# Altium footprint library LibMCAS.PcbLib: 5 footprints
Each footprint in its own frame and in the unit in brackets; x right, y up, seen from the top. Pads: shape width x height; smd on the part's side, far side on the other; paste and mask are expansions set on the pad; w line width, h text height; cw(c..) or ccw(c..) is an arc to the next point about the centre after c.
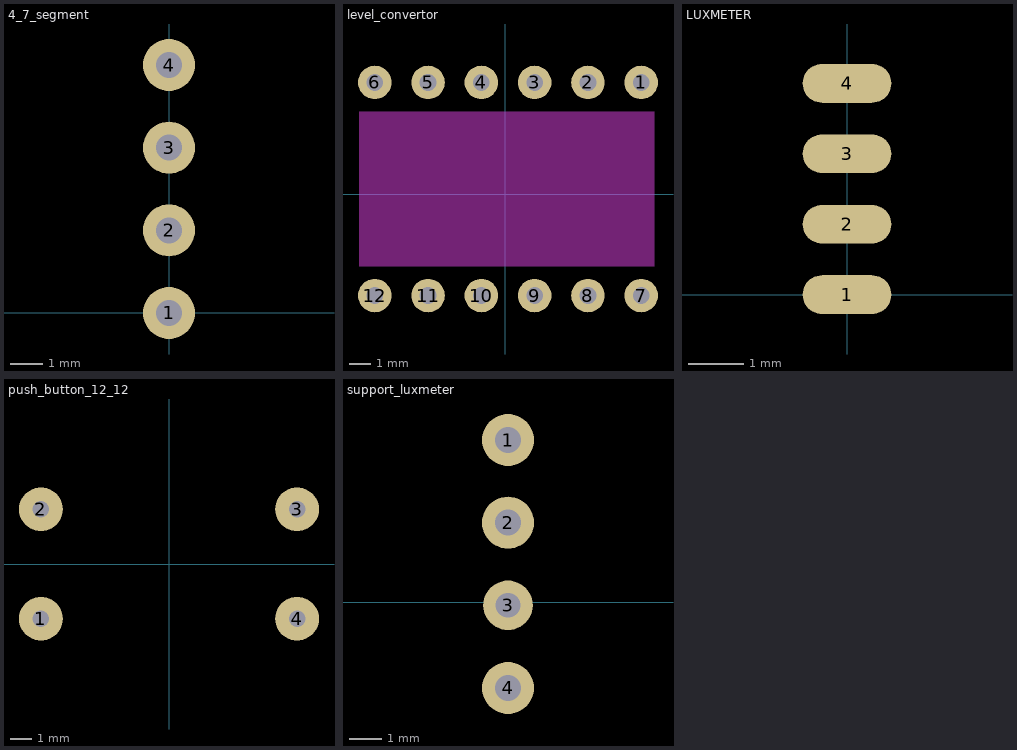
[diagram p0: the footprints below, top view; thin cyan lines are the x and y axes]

## 4_7_segment [mm]
pads (4):
  round 1.6 hole 0.8: 1(0,0) 2(0,2.54) 3(0,5.08) 4(0,7.62)
3D body "4_7_segment.step": height 15.5, standoff 0, extent -38.476,-8.198 1.524,14.802

## level_convertor [mm]
pads (12):
  round 1.6 hole 0.8: 1(6.477,5.334) 2(3.937,5.334) 3(1.397,5.334) 4(-1.143,5.334) 5(-3.683,5.334) 6(-6.223,5.334) 7(6.477,-4.826) 8(3.937,-4.826) 9(1.397,-4.826) 10(-1.143,-4.826) 11(-3.683,-4.826) 12(-6.223,-4.826)
Top Layer keep-out:
  rectangle: -6.985,-3.429 7.112,3.937

## LUXMETER [mm]
pads (4):
  oval 1.6x0.7 smd: 1(0,0) 2(0,1.27) 3(0,2.54) 4(0,3.81)

## push_button_12_12 [mm]
height 3.6
pads (4):
  round 2 hole 0.762: 1(-5.85,-2.5) 2(-5.85,2.5) 3(5.85,2.5) 4(5.85,-2.5)
3D body "button.step": height 12, standoff 0, extent -6,-6 6,6

## support_luxmeter [mm]
pads (4):
  round 1.6 hole 0.8: 1(10.873,4.992) 2(10.873,2.452) 4(10.873,-2.628)
  round 1.524 hole 0.762: 3(10.873,-0.088)
3D body "support_luxmeter.step": height 0, standoff -10, extent -4.238,-8.111 6.762,10.889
